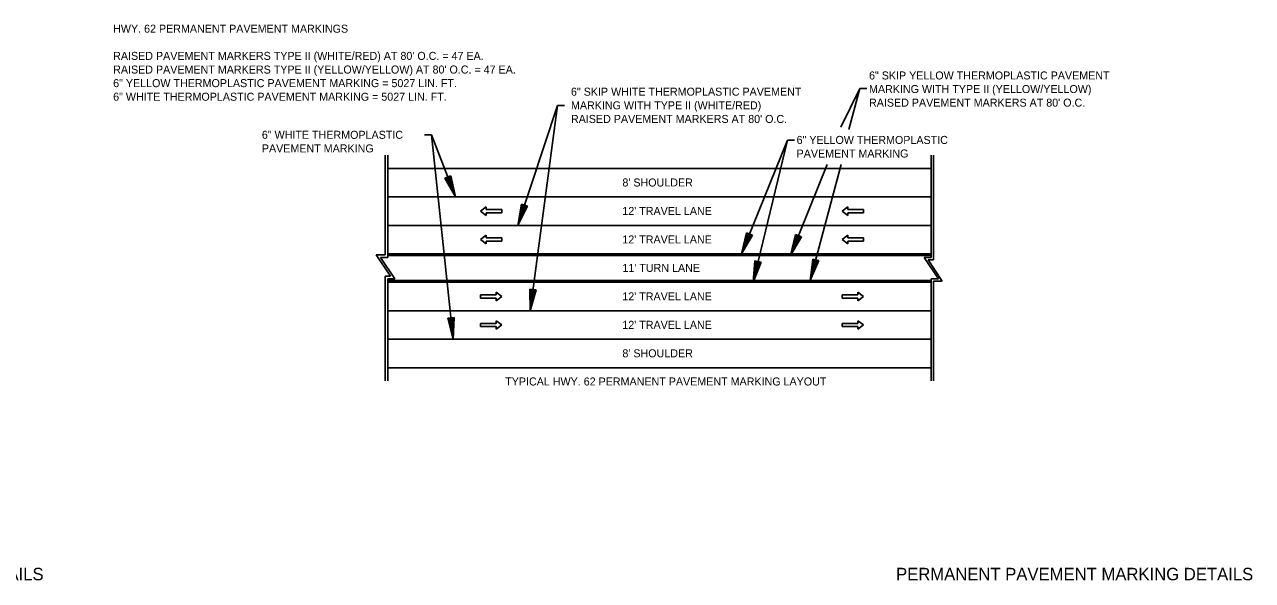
# Model space of a CAD drawing. Extents: x 2261938 to 2263136, y -3124572 to -3124216.
# Drawn here: x 2262623.7 to 2262796.3, y -3124313.5 to -3124235.4 of the extents above; entities that cross this region are included whole.
import ezdxf

# ---------------------------------------------------------------- set-up
doc = ezdxf.new("R2010")
doc.units = 0
doc.layers.add('Default', color=7, linetype='Continuous')
doc.layers.add('SHET_Border-Text', color=7, linetype='Continuous')

msp = doc.modelspace()

# ---------------------------------------------------------------- linework, layer by layer
at = {"layer": 'Default'}
for p, q in [((2262741.08, -3124244.38), (2262738.43, -3124249.81)), ((2262741.08, -3124244.38), (2262739.56, -3124250.11)), ((2262742.08, -3124244.38), (2262741.08, -3124244.38)), ((2262698.59, -3124246.74), (2262693.05, -3124263.6)), ((2262698.59, -3124246.74), (2262694.79, -3124275.6)), ((2262699.59, -3124246.74), (2262698.59, -3124246.74)), ((2262679.92, -3124250.88), (2262680.92, -3124250.88)), ((2262680.92, -3124250.88), (2262684.27, -3124259.6)), ((2262680.92, -3124250.88), (2262683.96, -3124279.6)), ((2262730.91, -3124251.63), (2262724.46, -3124267.6)), ((2262730.91, -3124251.63), (2262726.09, -3124271.6)), ((2262731.91, -3124251.63), (2262730.91, -3124251.63)), ((2262674.41, -3124253.76), (2262674.41, -3124267.76)), ((2262674.75, -3124253.76), (2262674.75, -3124268.1)), ((2262751.14, -3124253.76), (2262751.14, -3124268.1)), ((2262751.47, -3124253.76), (2262751.47, -3124268.43)), ((2262674.75, -3124255.6), (2262751.14, -3124255.6)), ((2262736.52, -3124255.06), (2262731.37, -3124267.85)), ((2262738.46, -3124255.05), (2262734.13, -3124271.35)), ((2262683.61, -3124256.64), (2262682.77, -3124256.96)), ((2262682.77, -3124256.96), (2262684.27, -3124259.6)), ((2262682.84, -3124256.93), (2262684.09, -3124259.13)), ((2262682.91, -3124256.9), (2262683.9, -3124258.65)), ((2262682.98, -3124256.88), (2262683.72, -3124258.18)), ((2262683.06, -3124256.85), (2262683.54, -3124257.71)), ((2262683.13, -3124256.82), (2262683.36, -3124257.24)), ((2262683.26, -3124256.77), (2262683.36, -3124257.24)), ((2262683.33, -3124256.74), (2262683.54, -3124257.71)), ((2262683.4, -3124256.72), (2262683.72, -3124258.18)), ((2262683.47, -3124256.69), (2262683.9, -3124258.65)), ((2262683.54, -3124256.66), (2262684.09, -3124259.13)), ((2262683.61, -3124256.64), (2262684.27, -3124259.6)), ((2262674.75, -3124259.6), (2262751.14, -3124259.6)), ((2262688.58, -3124261), (2262687.8, -3124261.6)), ((2262687.8, -3124261.6), (2262688.58, -3124262.2)), ((2262688.58, -3124261), (2262688.58, -3124261.37)), ((2262688.58, -3124261.37), (2262690.78, -3124261.37)), ((2262690.78, -3124261.37), (2262690.78, -3124261.82)), ((2262693.55, -3124260.61), (2262693.05, -3124263.6)), ((2262694.41, -3124260.89), (2262693.05, -3124263.6)), ((2262693.62, -3124260.63), (2262693.21, -3124263.12)), ((2262694.34, -3124260.86), (2262693.21, -3124263.12)), ((2262693.7, -3124260.65), (2262693.37, -3124262.63)), ((2262694.26, -3124260.84), (2262693.37, -3124262.63)), ((2262693.77, -3124260.68), (2262693.52, -3124262.16)), ((2262694.19, -3124260.82), (2262693.52, -3124262.16)), ((2262694.41, -3124260.89), (2262693.55, -3124260.61)), ((2262693.84, -3124260.7), (2262693.68, -3124261.67)), ((2262694.12, -3124260.79), (2262693.68, -3124261.67)), ((2262693.91, -3124260.72), (2262693.83, -3124261.2)), ((2262694.05, -3124260.77), (2262693.83, -3124261.2)), ((2262739.39, -3124261), (2262738.62, -3124261.6)), ((2262738.62, -3124261.6), (2262739.39, -3124262.2)), ((2262739.39, -3124261), (2262739.39, -3124261.37)), ((2262739.39, -3124261.37), (2262741.6, -3124261.37)), ((2262741.6, -3124261.37), (2262741.6, -3124261.82)), ((2262688.58, -3124261.82), (2262690.78, -3124261.82)), ((2262688.58, -3124261.82), (2262688.58, -3124262.2)), ((2262739.39, -3124261.82), (2262741.6, -3124261.82)), ((2262739.39, -3124261.82), (2262739.39, -3124262.2)), ((2262674.75, -3124263.6), (2262751.14, -3124263.6)), ((2262688.58, -3124265), (2262687.8, -3124265.6)), ((2262688.58, -3124265), (2262688.58, -3124265.37)), ((2262725.17, -3124264.65), (2262724.46, -3124267.6)), ((2262726, -3124264.98), (2262724.46, -3124267.6)), ((2262725.24, -3124264.68), (2262724.65, -3124267.13)), ((2262725.94, -3124264.96), (2262724.65, -3124267.13)), ((2262725.31, -3124264.7), (2262724.85, -3124266.65)), ((2262725.86, -3124264.93), (2262724.85, -3124266.65)), ((2262725.38, -3124264.73), (2262725.03, -3124266.19)), ((2262725.79, -3124264.9), (2262725.03, -3124266.19)), ((2262726, -3124264.98), (2262725.17, -3124264.65)), ((2262725.45, -3124264.76), (2262725.22, -3124265.72)), ((2262725.72, -3124264.87), (2262725.22, -3124265.72)), ((2262725.52, -3124264.79), (2262725.41, -3124265.26)), ((2262725.65, -3124264.84), (2262725.41, -3124265.26)), ((2262732.07, -3124264.9), (2262731.37, -3124267.85)), ((2262732.91, -3124265.23), (2262731.37, -3124267.85)), ((2262732.14, -3124264.93), (2262731.55, -3124267.38)), ((2262732.84, -3124265.21), (2262731.55, -3124267.38)), ((2262732.21, -3124264.95), (2262731.75, -3124266.9)), ((2262732.77, -3124265.18), (2262731.75, -3124266.9)), ((2262732.28, -3124264.98), (2262731.93, -3124266.44)), ((2262732.7, -3124265.15), (2262731.93, -3124266.44)), ((2262732.91, -3124265.23), (2262732.07, -3124264.9)), ((2262732.35, -3124265.01), (2262732.12, -3124265.97)), ((2262732.62, -3124265.12), (2262732.12, -3124265.97)), ((2262732.42, -3124265.04), (2262732.31, -3124265.51)), ((2262732.55, -3124265.09), (2262732.31, -3124265.51)), ((2262739.39, -3124265), (2262738.62, -3124265.6)), ((2262739.39, -3124265), (2262739.39, -3124265.37)), ((2262687.8, -3124265.6), (2262688.58, -3124266.2)), ((2262688.58, -3124265.37), (2262690.78, -3124265.37)), ((2262688.58, -3124265.82), (2262690.78, -3124265.82)), ((2262688.58, -3124265.82), (2262688.58, -3124266.2)), ((2262690.78, -3124265.37), (2262690.78, -3124265.82)), ((2262738.62, -3124265.6), (2262739.39, -3124266.2)), ((2262739.39, -3124265.37), (2262741.6, -3124265.37)), ((2262739.39, -3124265.82), (2262741.6, -3124265.82)), ((2262739.39, -3124265.82), (2262739.39, -3124266.2)), ((2262741.6, -3124265.37), (2262741.6, -3124265.82)), ((2262675.12, -3124270.76), (2262673.12, -3124267.76)), ((2262674.41, -3124267.76), (2262673.12, -3124267.76)), ((2262674.75, -3124268.1), (2262673.75, -3124268.1)), ((2262675.75, -3124271.1), (2262673.75, -3124268.1)), ((2262674.75, -3124267.6), (2262751.14, -3124267.6)), ((2262674.75, -3124267.85), (2262751.14, -3124267.85)), ((2262726.36, -3124268.58), (2262726.09, -3124271.6)), ((2262726.43, -3124268.59), (2262726.21, -3124271.11)), ((2262726.5, -3124268.61), (2262726.33, -3124270.61)), ((2262727.23, -3124268.79), (2262726.36, -3124268.58)), ((2262726.58, -3124268.63), (2262726.45, -3124270.12)), ((2262726.65, -3124268.65), (2262726.56, -3124269.63)), ((2262726.72, -3124268.67), (2262726.68, -3124269.14)), ((2262726.86, -3124268.7), (2262726.68, -3124269.14)), ((2262734.47, -3124268.33), (2262734.13, -3124271.35)), ((2262735.34, -3124268.56), (2262734.13, -3124271.35)), ((2262734.54, -3124268.35), (2262734.26, -3124270.86)), ((2262735.26, -3124268.54), (2262734.26, -3124270.86)), ((2262734.61, -3124268.37), (2262734.39, -3124270.36)), ((2262735.19, -3124268.52), (2262734.39, -3124270.36)), ((2262735.34, -3124268.56), (2262734.47, -3124268.33)), ((2262734.69, -3124268.39), (2262734.52, -3124269.88)), ((2262735.12, -3124268.51), (2262734.52, -3124269.88)), ((2262734.76, -3124268.41), (2262734.65, -3124269.39)), ((2262735.04, -3124268.49), (2262734.65, -3124269.39)), ((2262734.83, -3124268.43), (2262734.78, -3124268.91)), ((2262734.97, -3124268.47), (2262734.78, -3124268.91)), ((2262751.14, -3124268.1), (2262750.14, -3124268.1)), ((2262752.14, -3124271.1), (2262750.14, -3124268.1)), ((2262752.69, -3124271.43), (2262750.69, -3124268.43)), ((2262751.47, -3124268.43), (2262750.69, -3124268.43)), ((2262727.23, -3124268.79), (2262726.09, -3124271.6)), ((2262727.16, -3124268.77), (2262726.21, -3124271.11)), ((2262727.08, -3124268.75), (2262726.33, -3124270.61)), ((2262727.01, -3124268.73), (2262726.45, -3124270.12)), ((2262726.93, -3124268.72), (2262726.56, -3124269.63)), ((2262674.41, -3124270.76), (2262675.12, -3124270.76)), ((2262674.41, -3124285.43), (2262674.41, -3124270.76)), ((2262674.75, -3124285.43), (2262674.75, -3124271.1)), ((2262674.75, -3124271.1), (2262675.75, -3124271.1)), ((2262674.75, -3124271.35), (2262751.14, -3124271.35)), ((2262674.75, -3124271.6), (2262751.14, -3124271.6)), ((2262751.14, -3124285.43), (2262751.14, -3124271.1)), ((2262751.14, -3124271.1), (2262752.14, -3124271.1)), ((2262751.47, -3124285.43), (2262751.47, -3124271.43)), ((2262751.47, -3124271.43), (2262752.69, -3124271.43)), ((2262690, -3124273.37), (2262687.8, -3124273.37)), ((2262687.8, -3124273.37), (2262687.8, -3124273.82)), ((2262690, -3124273.82), (2262687.8, -3124273.82)), ((2262690, -3124273), (2262690, -3124273.37)), ((2262690, -3124273), (2262690.78, -3124273.6)), ((2262690.78, -3124273.6), (2262690, -3124274.2)), ((2262690, -3124273.82), (2262690, -3124274.2)), ((2262694.74, -3124272.56), (2262694.79, -3124275.6)), ((2262695.63, -3124272.68), (2262694.74, -3124272.56)), ((2262695.63, -3124272.68), (2262694.79, -3124275.6)), ((2262694.81, -3124272.57), (2262694.86, -3124275.1)), ((2262695.56, -3124272.67), (2262694.86, -3124275.1)), ((2262694.89, -3124272.58), (2262694.93, -3124274.59)), ((2262695.48, -3124272.66), (2262694.93, -3124274.59)), ((2262694.96, -3124272.59), (2262694.99, -3124274.09)), ((2262695.41, -3124272.65), (2262694.99, -3124274.09)), ((2262695.04, -3124272.6), (2262695.06, -3124273.59)), ((2262695.33, -3124272.64), (2262695.06, -3124273.59)), ((2262695.11, -3124272.61), (2262695.12, -3124273.09)), ((2262695.25, -3124272.63), (2262695.12, -3124273.09)), ((2262740.82, -3124273.37), (2262738.62, -3124273.37)), ((2262738.62, -3124273.37), (2262738.62, -3124273.82)), ((2262740.82, -3124273.82), (2262738.62, -3124273.82)), ((2262740.82, -3124273), (2262740.82, -3124273.37)), ((2262740.82, -3124273), (2262741.6, -3124273.6)), ((2262741.6, -3124273.6), (2262740.82, -3124274.2)), ((2262740.82, -3124273.82), (2262740.82, -3124274.2)), ((2262674.75, -3124275.6), (2262751.14, -3124275.6)), ((2262684.09, -3124276.57), (2262683.2, -3124276.66)), ((2262683.2, -3124276.66), (2262683.96, -3124279.6)), ((2262683.27, -3124276.65), (2262683.91, -3124279.1)), ((2262683.35, -3124276.65), (2262683.86, -3124278.59)), ((2262683.43, -3124276.64), (2262683.8, -3124278.09)), ((2262683.5, -3124276.63), (2262683.75, -3124277.58)), ((2262683.58, -3124276.62), (2262683.7, -3124277.09)), ((2262683.72, -3124276.61), (2262683.7, -3124277.09)), ((2262683.79, -3124276.6), (2262683.75, -3124277.58)), ((2262683.87, -3124276.59), (2262683.8, -3124278.09)), ((2262683.94, -3124276.58), (2262683.86, -3124278.59)), ((2262684.02, -3124276.58), (2262683.91, -3124279.1)), ((2262684.09, -3124276.57), (2262683.96, -3124279.6)), ((2262690, -3124277), (2262690, -3124277.37)), ((2262690, -3124277), (2262690.78, -3124277.6)), ((2262740.82, -3124277), (2262740.82, -3124277.37)), ((2262740.82, -3124277), (2262741.6, -3124277.6)), ((2262690, -3124277.37), (2262687.8, -3124277.37)), ((2262687.8, -3124277.37), (2262687.8, -3124277.82)), ((2262690, -3124277.82), (2262687.8, -3124277.82)), ((2262690.78, -3124277.6), (2262690, -3124278.2)), ((2262690, -3124277.82), (2262690, -3124278.2)), ((2262740.82, -3124277.37), (2262738.62, -3124277.37)), ((2262738.62, -3124277.37), (2262738.62, -3124277.82)), ((2262740.82, -3124277.82), (2262738.62, -3124277.82)), ((2262741.6, -3124277.6), (2262740.82, -3124278.2)), ((2262740.82, -3124277.82), (2262740.82, -3124278.2)), ((2262674.75, -3124279.6), (2262751.14, -3124279.6)), ((2262674.75, -3124283.6), (2262751.14, -3124283.6))]:
    msp.add_line(p, q, dxfattribs=at)

# ---------------------------------------------------------------- texts
for s, p in [('HWY. 62 PERMANENT PAVEMENT MARKINGS', (2262636.16, -3124236.53)), ("RAISED PAVEMENT MARKERS TYPE II (WHITE/RED) AT 80' O.C. = 47 EA.", (2262636.16, -3124240.35)), ("RAISED PAVEMENT MARKERS TYPE II (YELLOW/YELLOW) AT 80' O.C. = 47 EA.", (2262636.16, -3124242.27)), ('6" SKIP YELLOW THERMOPLASTIC PAVEMENT', (2262742.39, -3124243.1)), ('6" YELLOW THERMOPLASTIC PAVEMENT MARKING = 5027 LIN. FT.', (2262636.16, -3124244.18)), ('6" SKIP WHITE THERMOPLASTIC PAVEMENT', (2262700.5, -3124245.38)), ('MARKING WITH TYPE II (YELLOW/YELLOW)', (2262742.39, -3124245.01)), ('6" WHITE THERMOPLASTIC PAVEMENT MARKING = 5027 LIN. FT.', (2262636.16, -3124246.09)), ('MARKING WITH TYPE II (WHITE/RED)', (2262700.5, -3124247.3)), ("RAISED PAVEMENT MARKERS AT 80' O.C.", (2262742.39, -3124246.92)), ("RAISED PAVEMENT MARKERS AT 80' O.C.", (2262700.5, -3124249.21)), ('6" WHITE THERMOPLASTIC', (2262657.06, -3124251.44)), ('6" YELLOW THERMOPLASTIC', (2262732.21, -3124252.16)), ('PAVEMENT MARKING', (2262657.06, -3124253.35)), ('PAVEMENT MARKING', (2262732.21, -3124254.07)), ("8' SHOULDER", (2262707.73, -3124258.14)), ("12' TRAVEL LANE", (2262707.72, -3124262.14)), ("12' TRAVEL LANE", (2262707.72, -3124266.14)), ("11' TURN LANE", (2262707.73, -3124270.14)), ("12' TRAVEL LANE", (2262707.72, -3124274.14)), ("12' TRAVEL LANE", (2262707.72, -3124278.14)), ("8' SHOULDER", (2262707.73, -3124282.14)), ('TYPICAL HWY. 62 PERMANENT PAVEMENT MARKING LAYOUT', (2262691.26, -3124286.1))]:
    msp.add_text(s, height=1.125, dxfattribs=at).set_placement(p)
at = {"layer": 'SHET_Border-Text'}
for p in [(2262576.19, -3124313.47), (2262746.19, -3124313.47)]:
    msp.add_text('PERMANENT PAVEMENT MARKING DETAILS', height=1.75, dxfattribs=at).set_placement(p)

doc.saveas('drawing.dxf')
